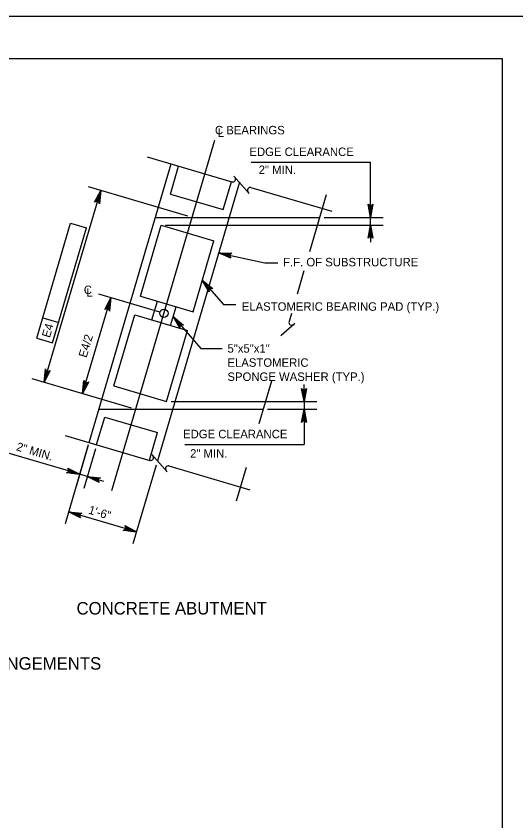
# Model space of a CAD drawing. Extents: x 638268 to 640277, y 295465 to 298435.
# Drawn here: x 639930.1 to 640107.3, y 298150.4 to 298435.5 of the extents above; entities that cross this region are included whole.
import ezdxf

# ---------------------------------------------------------------- set-up
doc = ezdxf.new("R2010")
doc.units = 0
for name, color, linetype in [('2', 7, 'Continuous'), ('3', 7, 'Continuous'), ('4', 7, 'Continuous'), ('7', 7, 'Continuous'), ('PLT-BNDY', 7, 'Continuous')]:
    doc.layers.add(name, color=color, linetype=linetype)

msp = doc.modelspace()

# ---------------------------------------------------------------- linework, layer by layer
at = {"layer": '2'}
for p, q in [((639316.46, 298420.46), (640102.46, 298420.46)), ((640102.46, 298420.46), (640102.46, 297856.46))]:
    msp.add_line(p, q, dxfattribs=at)
at = {"layer": '3'}
for p, q in [((639976.64, 298385.58), (640006.65, 298376.74)), ((639956, 298284.45), (639985.06, 298383.1)), ((640007.35, 298378.81), (640012.76, 298372.67)), ((640009.31, 298376.59), (639980.25, 298277.94)), ((640013.36, 298374.77), (640042.04, 298366.32)), ((639984.84, 298372.42), (640003.53, 298366.91)), ((640040.1, 298372.12), (640034.17, 298351.98)), ((639979.48, 298364.16), (640037.75, 298364.16)), ((639981.59, 298361.4), (640000.29, 298355.9)), ((640032.19, 298345.26), (640029.75, 298337)), ((639974.18, 298336.22), (639992.87, 298330.72)), ((639972.23, 298329.62), (639990.93, 298324.11)), ((640027.74, 298330.15), (640026.88, 298327.24)), ((640028.94, 298326.55), (640024.04, 298322.22)), ((640020.65, 298306.11), (640016.22, 298291.07)), ((639964.82, 298304.44), (639983.51, 298298.93)), ((639959.46, 298296.18), (640017.73, 298296.18)), ((639961.57, 298293.42), (639980.27, 298287.92)), ((639947.59, 298286.93), (639977.6, 298278.09)), ((639978.29, 298280.16), (639983.71, 298274.02)), ((639984.31, 298276.12), (640012.99, 298267.67)), ((640011.67, 298275.6), (640008.14, 298263.61))]:
    msp.add_line(p, q, dxfattribs=at)
for centre, start, end in [((640006.95, 298377.72), 253.588, 43.588), ((640013.17, 298373.76), 78.9166, 221.4552), ((640027.86, 298326.95), 163.588, 313.588), ((639977.89, 298279.08), 253.588, 43.588), ((639984.11, 298275.11), 78.9166, 221.4552)]:
    msp.add_arc(centre, 1.02, start, end, dxfattribs=at)
at = {"layer": '4'}
for p, q in [((639964.05, 298267.37), (640000.6, 298391.45)), ((640013.49, 298383.7), (640055.76, 298383.7)), ((640055.76, 298367.16), (640055.76, 298383.7)), ((639991.06, 298364.6), (639955.81, 298374.98)), ((639940.1, 298305.73), (639960.13, 298373.71)), ((640039.32, 298364.16), (640060.26, 298364.16)), ((640055.76, 298361.4), (640055.76, 298364.16)), ((639937.44, 298321.33), (639949.45, 298362.12)), ((639943.1, 298319.67), (639955.11, 298360.45)), ((639949.45, 298362.12), (639955.11, 298360.45)), ((639983.15, 298361.4), (640060.26, 298361.4)), ((640055.76, 298358.4), (640055.76, 298355.4)), ((640018.31, 298348.09), (640022.87, 298348.09)), ((639953.73, 298301.72), (639963.74, 298335.71)), ((639981.05, 298330.61), (639959.43, 298336.98)), ((640003.66, 298333.25), (640008.01, 298333.25)), ((639939.57, 298328.59), (639945.24, 298326.92)), ((639937.44, 298321.33), (639943.1, 298319.67)), ((639995.57, 298317.67), (640003.23, 298317.67)), ((639971.04, 298296.62), (639935.79, 298307)), ((639971.04, 298296.62), (639949.41, 298302.99)), ((640032.23, 298301.93), (640032.23, 298304.93)), ((639985.07, 298298.93), (640036.73, 298298.93)), ((640032.23, 298298.93), (640032.23, 298296.18)), ((640019.29, 298296.18), (640036.73, 298296.18)), ((640032.23, 298293.18), (640032.23, 298283.71)), ((639955.73, 298283.53), (639947.5, 298255.59)), ((639955.56, 298282.96), (639951.42, 298268.88)), ((639989.97, 298283.71), (640032.23, 298283.71)), ((639952.69, 298273.2), (639927.34, 298280.66)), ((639958.25, 298282.16), (639954.11, 298268.09)), ((639979.81, 298276.44), (639971.58, 298248.5)), ((639955.38, 298272.4), (639952.69, 298273.2)), ((639955.38, 298272.4), (639961.13, 298270.71)), ((639972.85, 298252.81), (639948.77, 298259.91))]:
    msp.add_line(p, q, dxfattribs=at)
for points in [[(639960.13, 298373.71), (639959.65, 298369), (639959.51, 298369.41), (639959.26, 298369.67), (639958.98, 298369.81), (639958.66, 298369.85), (639958.31, 298369.76), (639957.97, 298369.49), (639960.13, 298373.71), (639958.31, 298369.76), (639958.66, 298369.85), (639960.13, 298373.71), (639958.98, 298369.81), (639959.26, 298369.67), (639960.13, 298373.71), (639959.51, 298369.41)], [(640055.76, 298364.16), (640054.89, 298368.82), (640055.13, 298368.46), (640055.45, 298368.27), (640055.76, 298368.22), (640056.07, 298368.27), (640056.38, 298368.46), (640056.63, 298368.82), (640055.76, 298364.16), (640056.38, 298368.46), (640056.07, 298368.27), (640055.76, 298364.16), (640055.76, 298368.22), (640055.45, 298368.27), (640055.76, 298364.16), (640055.13, 298368.46)], [(640055.76, 298361.4), (640056.63, 298356.74), (640056.38, 298357.1), (640056.07, 298357.29), (640055.76, 298357.34), (640055.45, 298357.29), (640055.13, 298357.1), (640054.89, 298356.74), (640055.76, 298361.4), (640055.13, 298357.1), (640055.45, 298357.29), (640055.76, 298361.4), (640055.76, 298357.34), (640056.07, 298357.29), (640055.76, 298361.4), (640056.38, 298357.1)], [(640001.93, 298351.54), (640018.31, 298348.09)], [(640001.93, 298351.54), (640006.67, 298351.44), (640006.27, 298351.27), (640006.02, 298351), (640005.9, 298350.7), (640005.89, 298350.39), (640006.01, 298350.04), (640006.31, 298349.73), (640001.93, 298351.54), (640006.01, 298350.04), (640005.89, 298350.39), (640001.93, 298351.54), (640005.9, 298350.7), (640006.02, 298351), (640001.93, 298351.54), (640006.27, 298351.27)], [(639996.15, 298341.86), (640003.66, 298333.25)], [(639996.15, 298341.86), (639999.87, 298338.92), (639999.45, 298339.02), (639999.09, 298338.96), (639998.82, 298338.79), (639998.62, 298338.55), (639998.51, 298338.2), (639998.55, 298337.77), (639996.15, 298341.86), (639998.51, 298338.2), (639998.62, 298338.55), (639996.15, 298341.86), (639998.82, 298338.79), (639999.09, 298338.96), (639996.15, 298341.86), (639999.45, 298339.02)], [(639963.74, 298335.71), (639963.27, 298330.99), (639963.13, 298331.41), (639962.88, 298331.67), (639962.6, 298331.81), (639962.28, 298331.85), (639961.93, 298331.76), (639961.59, 298331.48), (639963.74, 298335.71), (639961.93, 298331.76), (639962.28, 298331.85), (639963.74, 298335.71), (639962.6, 298331.81), (639962.88, 298331.67), (639963.74, 298335.71), (639963.13, 298331.41)], [(639985.8, 298328.99), (639995.57, 298317.67)], [(639985.8, 298328.99), (639989.5, 298326.03), (639989.08, 298326.14), (639988.72, 298326.08), (639988.45, 298325.92), (639988.25, 298325.67), (639988.13, 298325.33), (639988.18, 298324.89), (639985.8, 298328.99), (639988.13, 298325.33), (639988.25, 298325.67), (639985.8, 298328.99), (639988.45, 298325.92), (639988.72, 298326.08), (639985.8, 298328.99), (639989.08, 298326.14)], [(639940.1, 298305.73), (639940.58, 298310.45), (639940.72, 298310.03), (639940.97, 298309.77), (639941.25, 298309.63), (639941.57, 298309.59), (639941.92, 298309.68), (639942.26, 298309.96), (639940.1, 298305.73), (639941.92, 298309.68), (639941.57, 298309.59), (639940.1, 298305.73), (639941.25, 298309.63), (639940.97, 298309.77), (639940.1, 298305.73), (639940.72, 298310.03)], [(639953.73, 298301.72), (639954.21, 298306.43), (639954.35, 298306.02), (639954.59, 298305.76), (639954.88, 298305.62), (639955.19, 298305.58), (639955.55, 298305.67), (639955.89, 298305.94), (639953.73, 298301.72), (639955.55, 298305.67), (639955.19, 298305.58), (639953.73, 298301.72), (639954.88, 298305.62), (639954.59, 298305.76), (639953.73, 298301.72), (639954.35, 298306.02)], [(640032.23, 298298.93), (640031.36, 298303.6), (640031.61, 298303.24), (640031.92, 298303.05), (640032.23, 298303), (640032.55, 298303.05), (640032.86, 298303.24), (640033.11, 298303.6), (640032.23, 298298.93), (640032.86, 298303.24), (640032.55, 298303.05), (640032.23, 298298.93), (640032.23, 298303), (640031.92, 298303.05), (640032.23, 298298.93), (640031.61, 298303.24)], [(640032.23, 298296.18), (640033.11, 298291.52), (640032.86, 298291.88), (640032.55, 298292.06), (640032.23, 298292.12), (640031.92, 298292.06), (640031.61, 298291.88), (640031.36, 298291.52), (640032.23, 298296.18), (640031.61, 298291.88), (640031.92, 298292.06), (640032.23, 298296.18), (640032.23, 298292.12), (640032.55, 298292.06), (640032.23, 298296.18), (640032.86, 298291.88)], [(639952.69, 298273.2), (639947.97, 298273.67), (639948.39, 298273.81), (639948.65, 298274.06), (639948.79, 298274.34), (639948.83, 298274.66), (639948.74, 298275.01), (639948.46, 298275.35), (639952.69, 298273.2), (639948.74, 298275.01), (639948.83, 298274.66), (639952.69, 298273.2), (639948.79, 298274.34), (639948.65, 298274.06), (639952.69, 298273.2), (639948.39, 298273.81)], [(639955.38, 298272.4), (639960.09, 298271.92), (639959.68, 298271.79), (639959.41, 298271.54), (639959.28, 298271.26), (639959.24, 298270.94), (639959.33, 298270.59), (639959.6, 298270.25), (639955.38, 298272.4), (639959.33, 298270.59), (639959.24, 298270.94), (639955.38, 298272.4), (639959.28, 298271.26), (639959.41, 298271.54), (639955.38, 298272.4), (639959.68, 298271.79)], [(639948.77, 298259.91), (639953.49, 298259.43), (639953.08, 298259.29), (639952.81, 298259.04), (639952.67, 298258.76), (639952.63, 298258.44), (639952.72, 298258.09), (639953, 298257.75), (639948.77, 298259.91), (639952.72, 298258.09), (639952.63, 298258.44), (639948.77, 298259.91), (639952.67, 298258.76), (639952.81, 298259.04), (639948.77, 298259.91), (639953.08, 298259.29)], [(639972.85, 298252.81), (639968.13, 298253.29), (639968.55, 298253.43), (639968.81, 298253.68), (639968.95, 298253.96), (639968.99, 298254.28), (639968.9, 298254.63), (639968.63, 298254.97), (639972.85, 298252.81), (639968.9, 298254.63), (639968.99, 298254.28), (639972.85, 298252.81), (639968.95, 298253.96), (639968.81, 298253.68), (639972.85, 298252.81), (639968.55, 298253.43)]]:
    msp.add_lwpolyline(points, dxfattribs=at)
for points in [[(639958.8, 298370.97), (639959.76, 298370.69), (639960.13, 298373.71)], [(640055.26, 298367.16), (640056.26, 298367.16), (640055.76, 298364.16)], [(640055.26, 298358.4), (640056.26, 298358.4), (640055.76, 298361.4)], [(640001.93, 298351.54), (640004.81, 298350.68), (640004.92, 298351.17)], [(639996.15, 298341.86), (639997.94, 298339.43), (639998.31, 298339.76)], [(639962.42, 298332.97), (639963.38, 298332.69), (639963.74, 298335.71)], [(639985.8, 298328.99), (639987.57, 298326.56), (639987.94, 298326.88)], [(639940.47, 298308.75), (639941.43, 298308.47), (639940.1, 298305.73)], [(639954.1, 298304.74), (639955.06, 298304.45), (639953.73, 298301.72)], [(640031.73, 298301.93), (640032.73, 298301.93), (640032.23, 298298.93)], [(640031.73, 298293.18), (640032.73, 298293.18), (640032.23, 298296.18)], [(639949.95, 298274.52), (639949.67, 298273.56), (639952.69, 298273.2)], [(639958.4, 298272.04), (639958.11, 298271.08), (639955.38, 298272.4)], [(639951.79, 298259.54), (639951.51, 298258.58), (639948.77, 298259.91)], [(639970.11, 298254.14), (639969.83, 298253.18), (639972.85, 298252.81)]]:
    msp.add_lwpolyline(points, close=True, dxfattribs=at)
at = {"layer": '7'}
for p, q in [((639984.84, 298372.42), (639987.75, 298382.31)), ((640003.53, 298366.91), (640006.45, 298376.8)), ((639974.18, 298336.22), (639981.59, 298361.4)), ((639992.87, 298330.72), (640000.29, 298355.9)), ((639978.27, 298327.84), (639980.22, 298334.45)), ((639984.88, 298325.89), (639986.83, 298332.5)), ((639964.82, 298304.44), (639972.23, 298329.62)), ((639983.51, 298298.93), (639990.93, 298324.11)), ((639958.69, 298283.66), (639961.57, 298293.42)), ((639977.39, 298278.16), (639980.27, 298287.92))]:
    msp.add_line(p, q, dxfattribs=at)
msp.add_circle((639982.55, 298330.17), 1.48, dxfattribs=at)
at = {"layer": 'PLT-BNDY'}
msp.add_lwpolyline([(639276.46, 298435.46), (640117.46, 298435.46), (640117.46, 297841.46), (639276.46, 297841.46)], close=True, dxfattribs=at)

# ---------------------------------------------------------------- texts
at = {"layer": '3'}
for s, p in [('CONCRETE ABUTMENT', (639951.57, 298223.48)), ('ELASTOMERIC BEARING PAD ARRANGEMENTS', (639824.06, 298203.94))]:
    msp.add_text(s, height=4.4292, dxfattribs=at).set_placement(p)
at = {"layer": '4'}
for s, p in [('C BEARINGS', (640000.63, 298393.56)), ('L', (640001.58, 298392.65)), ('EDGE CLEARANCE', (640012.84, 298385.89)), ('2" MIN.', (640016.13, 298379.51)), ('F.F. OF SUBSTRUCTURE', (640024.79, 298346.81)), ('C', (639954.15, 298336.99)), ('L', (639955.1, 298336.08)), ('ELASTOMERIC BEARING PAD (TYP.)', (640010.13, 298331.08)), ('5"x5"x1"', (640005.06, 298316.23)), ('ELASTOMERIC', (640005.06, 298311.23)), ('SPONGE WASHER (TYP.)', (640005.06, 298306.23)), ('EDGE CLEARANCE', (639989.32, 298285.91)), ('2" MIN.', (639991.82, 298279.03))]:
    msp.add_text(s, height=3, dxfattribs=at).set_placement(p)
for s, rotation, p in [('E4', 73.5262, (639942.08, 298321.33)), ('E4/2', 73.588, (639955.1, 298314.26)), ('2" MIN.', 343.588, (639929.99, 298281.69)), ('1\'-6"', 343.588, (639955.55, 298259.28))]:
    msp.add_text(s, height=3, rotation=rotation, dxfattribs=at).set_placement(p)

doc.saveas('drawing.dxf')
